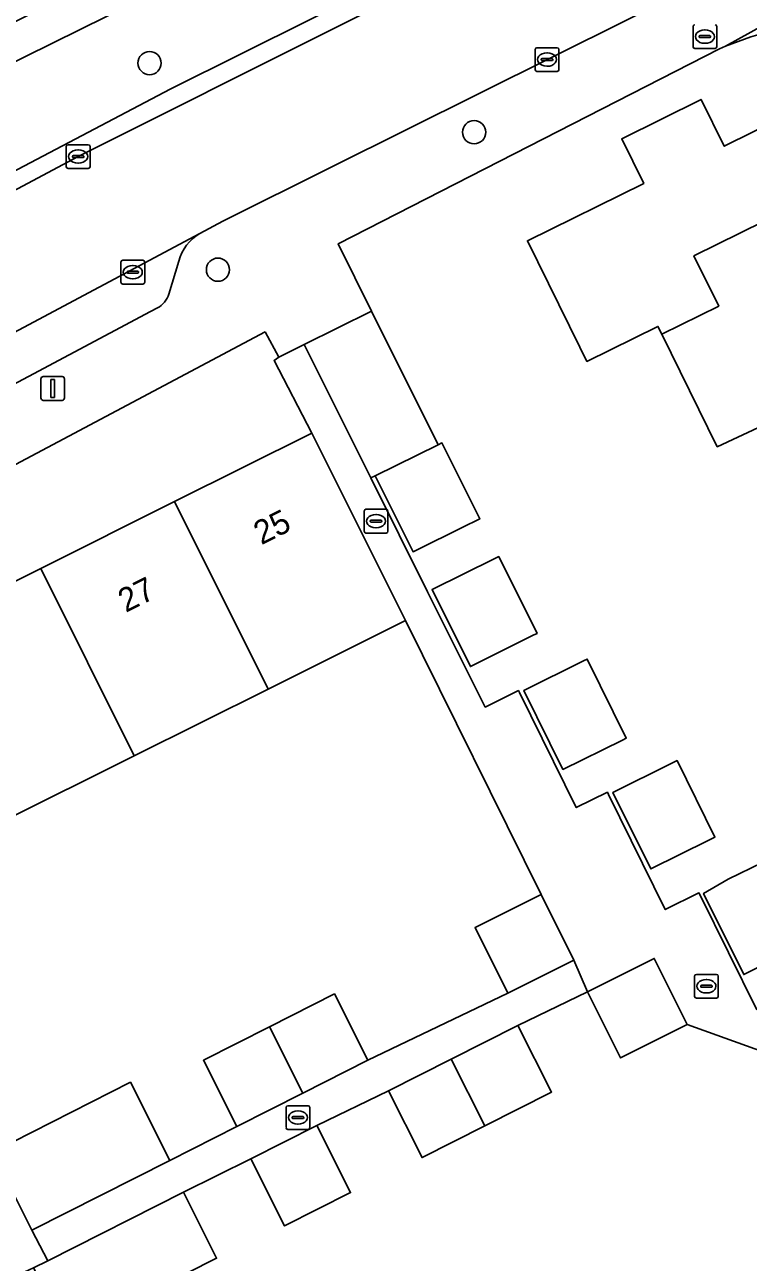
# Model space of a CAD drawing. Extents: x 157793 to 159380, y 380877 to 382313.
# Drawn here: x 158240.9 to 158271.4, y 381573.6 to 381625.7 of the extents above; entities that cross this region are included whole.
import ezdxf

# ---------------------------------------------------------------- set-up
doc = ezdxf.new("R2010")
doc.units = 0
for name, color, linetype in [('IMGEO_Boom', 7, 'Continuous'), ('IMGEO_Brandkraan', 7, 'Continuous'), ('IMGEO_Erf', 7, 'Continuous'), ('IMGEO_Groenvoorziening', 7, 'Continuous'), ('IMGEO_Kolk', 7, 'Continuous'), ('IMGEO_Lichtmast', 7, 'Continuous'), ('IMGEO_Pand', 7, 'Continuous'), ('IMGEO_Pand_nummerreeks', 7, 'Continuous'), ('IMGEO_Parkeervlak_open', 7, 'Continuous'), ('IMGEO_Rijbaan_lokaal_open', 7, 'Continuous'), ('IMGEO_Voetpad_halfverhard', 7, 'Continuous'), ('IMGEO_Voetpad_open', 7, 'Continuous')]:
    doc.layers.add(name, color=color, linetype=linetype)

msp = doc.modelspace()

# ---------------------------------------------------------------- linework, layer by layer
at = {"layer": 'IMGEO_Boom'}
for centre in [(158246.129, 381624.102), (158259.803, 381621.19), (158249.009, 381615.397)]:
    msp.add_circle(centre, 0.489, dxfattribs=at)
at = {"layer": 'IMGEO_Brandkraan'}
for p, q in [((158269.025, 381624.791), (158269.025, 381625.643)), ((158269.513, 381625.497), (158269.538, 381625.497)), ((158270.026, 381625.643), (158270.026, 381624.791)), ((158269.284, 381625.211), (158269.284, 381625.223)), ((158269.722, 381625.174), (158269.324, 381625.174)), ((158269.327, 381625.26), (158269.725, 381625.26)), ((158269.536, 381624.937), (158269.511, 381624.937)), ((158269.768, 381625.223), (158269.768, 381625.211)), ((158269.952, 381624.717), (158269.1, 381624.717))]:
    msp.add_line(p, q, dxfattribs=at)
for points in [[(158269.025, 381624.791), (158269.025, 381625.643)], [(158270.026, 381625.643), (158270.026, 381624.791)], [(158269.952, 381624.717), (158269.1, 381624.717)]]:
    msp.add_lwpolyline(points, dxfattribs=at)
for centre, radius, start, end in [((158269.102, 381625.641), 0.0765, 91.552, 178.448), ((158269.102, 381625.641), 0.0765, 91.552, 178.448), ((158269.95, 381625.641), 0.0765, 1.552, 88.448), ((158269.95, 381625.641), 0.0765, 1.552, 88.448), ((158269.324, 381625.22), 0.0403, 85.8775, 175.7526), ((158269.321, 381625.21), 0.0366, 178.938, 274.7102), ((158269.725, 381625.217), 0.043, 264.8664, 352.4533), ((158269.729, 381625.222), 0.0386, 1.7309, 96.639), ((158269.102, 381624.793), 0.0765, 181.552, 268.448), ((158269.102, 381624.793), 0.0765, 181.552, 268.448), ((158269.95, 381624.793), 0.0765, 271.552, 358.448), ((158269.95, 381624.793), 0.0765, 271.552, 358.448)]:
    msp.add_arc(centre, radius, start, end, dxfattribs=at)
for centre, major_axis, ratio, start_param, end_param in [((158269.512, 381625.217), (-0.387, 0.002), 0.722429, 4.712389, 7.853982), ((158269.537, 381625.217), (-0.39, 0.002), 0.717154, 1.570796, 4.712389)]:
    msp.add_ellipse(centre, major_axis=major_axis, ratio=ratio, start_param=start_param, end_param=end_param, dxfattribs=at)
at = {"layer": 'IMGEO_Erf'}
for points in [[(158271.454, 381625.214), (158270.397, 381624.809), (158270.144, 381624.696), (158254.068, 381616.48), (158255.473, 381613.653), (158258.284, 381608.021), (158258.447, 381608.102), (158260.044, 381604.902), (158259.881, 381604.821), (158259.473, 381604.62), (158257.234, 381603.513), (158255.637, 381606.713), (158255.452, 381606.621), (158257.845, 381601.827), (158260.271, 381596.966), (158261.671, 381597.665), (158261.712, 381597.581), (158264.106, 381592.734), (158265.416, 381593.381), (158265.464, 381593.284), (158267.858, 381588.438), (158269.275, 381589.138), (158269.324, 381589.038), (158271.708, 381584.211)], [(158273.078, 381609.359), (158270.049, 381607.94), (158267.707, 381612.68), (158267.546, 381613.006), (158264.558, 381611.53), (158264.261, 381612.131), (158262.047, 381616.614), (158266.949, 381619.035), (158266.02, 381620.916), (158269.365, 381622.569), (158270.338, 381620.598), (158275.287, 381623.042)], [(158272.878, 381582.118), (158268.783, 381583.589), (158265.976, 381582.187), (158264.582, 381584.978), (158261.649, 381583.558), (158263.069, 381580.749), (158260.254, 381579.326), (158257.611, 381577.99), (158256.191, 381580.799), (158253.173, 381579.335), (158254.598, 381576.517), (158251.816, 381575.111), (158250.391, 381577.929), (158247.551, 381576.528), (158248.955, 381573.75), (158242.644, 381570.559)]]:
    msp.add_lwpolyline(points, dxfattribs=at)
for points in [[(158251.002, 381612.779), (158228.387, 381600.769), (158230.119, 381597.11), (158235.907, 381599.999), (158241.544, 381602.813), (158247.181, 381605.626), (158252.968, 381608.515), (158251.372, 381611.578), (158251.569, 381611.717)], [(158260.677, 381603.227), (158260.84, 381603.308), (158262.454, 381600.075), (158262.291, 381599.994), (158261.93, 381599.813), (158259.649, 381598.675), (158258.03, 381601.918)], [(158239.504, 381578.222), (158245.321, 381581.163), (158246.986, 381577.872), (158249.811, 381579.296), (158248.398, 381582.092), (158251.186, 381583.502), (158253.916, 381584.882), (158255.329, 381582.086), (158261.224, 381584.916), (158259.842, 381587.684), (158262.626, 381589.074), (158256.91, 381600.62), (158251.122, 381597.731), (158245.486, 381594.918), (158239.852, 381592.105), (158234.06, 381589.214)], [(158264.405, 381598.913), (158264.566, 381598.993), (158266.212, 381595.66), (158266.051, 381595.58), (158263.545, 381594.343), (158261.899, 381597.674)], [(158268.106, 381594.59), (158268.356, 381594.713), (158269.948, 381591.49), (158269.698, 381591.367), (158267.243, 381590.154), (158265.651, 381593.376)], [(158271.947, 381590.428), (158272.154, 381590.53), (158273.877, 381587.042), (158273.67, 381586.94), (158271.16, 381585.698), (158269.469, 381589.121), (158270.512, 381589.719)]]:
    msp.add_lwpolyline(points, close=True, dxfattribs=at)
at = {"layer": 'IMGEO_Groenvoorziening'}
for points in [[(158274.259, 381634.674), (158274.211, 381635.262), (158273.634, 381636.615), (158273.46, 381636.828), (158273.2, 381636.691), (158271.78, 381639.651), (158227.145, 381617.595), (158227.622, 381616.703), (158224.921, 381615.32), (158224.432, 381616.254), (158214.514, 381611.353)], [(158247.025, 381623.023), (158264.685, 381631.821), (158269.039, 381633.802)], [(158214.656, 381609.979), (158219.226, 381607.367), (158219.424, 381607.478), (158218.689, 381607.912), (158224.718, 381611.289), (158247.025, 381623.023)]]:
    msp.add_lwpolyline(points, dxfattribs=at)
at = {"layer": 'IMGEO_Kolk'}
for p, q in [((158262.374, 381623.824), (158262.374, 381624.676)), ((158262.449, 381624.75), (158263.301, 381624.75)), ((158262.862, 381624.53), (158262.887, 381624.53)), ((158263.375, 381624.676), (158263.375, 381623.824)), ((158262.633, 381624.244), (158262.633, 381624.256)), ((158263.071, 381624.207), (158262.673, 381624.207)), ((158262.676, 381624.293), (158263.074, 381624.293)), ((158262.885, 381623.97), (158262.86, 381623.97)), ((158263.117, 381624.256), (158263.117, 381624.244)), ((158263.301, 381623.75), (158262.449, 381623.75)), ((158242.619, 381619.738), (158242.619, 381620.59)), ((158242.694, 381620.664), (158243.546, 381620.664)), ((158242.921, 381620.207), (158243.319, 381620.207)), ((158243.107, 381620.444), (158243.132, 381620.444)), ((158243.62, 381620.59), (158243.62, 381619.738)), ((158243.546, 381619.664), (158242.694, 381619.664)), ((158242.878, 381620.158), (158242.878, 381620.17)), ((158243.316, 381620.121), (158242.918, 381620.121)), ((158243.13, 381619.884), (158243.105, 381619.884)), ((158243.362, 381620.17), (158243.362, 381620.158)), ((158244.921, 381614.867), (158244.921, 381615.719)), ((158244.996, 381615.793), (158245.848, 381615.793)), ((158245.409, 381615.573), (158245.434, 381615.573)), ((158245.922, 381615.719), (158245.922, 381614.867)), ((158245.18, 381615.287), (158245.18, 381615.299)), ((158245.618, 381615.25), (158245.22, 381615.25)), ((158245.223, 381615.336), (158245.621, 381615.336)), ((158245.432, 381615.013), (158245.407, 381615.013)), ((158245.664, 381615.299), (158245.664, 381615.287)), ((158245.848, 381614.793), (158244.996, 381614.793)), ((158255.169, 381604.375), (158255.169, 381605.227)), ((158255.244, 381605.301), (158256.096, 381605.301)), ((158255.657, 381605.081), (158255.682, 381605.081)), ((158256.17, 381605.227), (158256.17, 381604.375)), ((158255.428, 381604.795), (158255.428, 381604.807)), ((158255.866, 381604.758), (158255.468, 381604.758)), ((158255.471, 381604.844), (158255.869, 381604.844)), ((158255.912, 381604.807), (158255.912, 381604.795)), ((158256.096, 381604.301), (158255.244, 381604.301)), ((158255.68, 381604.521), (158255.655, 381604.521)), ((158269.09, 381584.78), (158269.09, 381585.632)), ((158269.165, 381585.706), (158270.017, 381585.706)), ((158269.578, 381585.486), (158269.603, 381585.486)), ((158270.091, 381585.632), (158270.091, 381584.78)), ((158269.349, 381585.2), (158269.349, 381585.212)), ((158269.787, 381585.163), (158269.389, 381585.163)), ((158269.392, 381585.249), (158269.79, 381585.249)), ((158269.601, 381584.926), (158269.576, 381584.926)), ((158269.833, 381585.212), (158269.833, 381585.2)), ((158270.017, 381584.706), (158269.165, 381584.706)), ((158251.88, 381579.249), (158251.88, 381580.101)), ((158251.955, 381580.175), (158252.807, 381580.175)), ((158252.881, 381580.101), (158252.881, 381579.249)), ((158252.139, 381579.669), (158252.139, 381579.681)), ((158252.577, 381579.632), (158252.179, 381579.632)), ((158252.182, 381579.718), (158252.58, 381579.718)), ((158252.368, 381579.955), (158252.393, 381579.955)), ((158252.623, 381579.681), (158252.623, 381579.669)), ((158252.807, 381579.175), (158251.955, 381579.175)), ((158252.391, 381579.395), (158252.366, 381579.395))]:
    msp.add_line(p, q, dxfattribs=at)
for points in [[(158262.374, 381623.824), (158262.374, 381624.676)], [(158262.449, 381624.75), (158263.301, 381624.75)], [(158263.375, 381624.676), (158263.375, 381623.824)], [(158263.301, 381623.75), (158262.449, 381623.75)], [(158242.619, 381619.738), (158242.619, 381620.59)], [(158242.694, 381620.664), (158243.546, 381620.664)], [(158243.62, 381620.59), (158243.62, 381619.738)], [(158243.546, 381619.664), (158242.694, 381619.664)], [(158244.921, 381614.867), (158244.921, 381615.719)], [(158244.996, 381615.793), (158245.848, 381615.793)], [(158245.922, 381615.719), (158245.922, 381614.867)], [(158245.848, 381614.793), (158244.996, 381614.793)], [(158255.169, 381604.375), (158255.169, 381605.227)], [(158255.244, 381605.301), (158256.096, 381605.301)], [(158256.17, 381605.227), (158256.17, 381604.375)], [(158256.096, 381604.301), (158255.244, 381604.301)], [(158269.09, 381584.78), (158269.09, 381585.632)], [(158269.165, 381585.706), (158270.017, 381585.706)], [(158270.091, 381585.632), (158270.091, 381584.78)], [(158270.017, 381584.706), (158269.165, 381584.706)], [(158251.88, 381579.249), (158251.88, 381580.101)], [(158251.955, 381580.175), (158252.807, 381580.175)], [(158252.881, 381580.101), (158252.881, 381579.249)], [(158252.807, 381579.175), (158251.955, 381579.175)]]:
    msp.add_lwpolyline(points, dxfattribs=at)
for centre, radius, start, end in [((158262.451, 381624.674), 0.0765, 91.552, 178.448), ((158262.451, 381624.674), 0.0765, 91.552, 178.448), ((158263.299, 381624.674), 0.0765, 1.552, 88.448), ((158263.299, 381624.674), 0.0765, 1.552, 88.448), ((158262.673, 381624.253), 0.0403, 85.8775, 175.7526), ((158262.67, 381624.243), 0.0366, 178.938, 274.7102), ((158263.074, 381624.25), 0.043, 264.8664, 352.4533), ((158263.078, 381624.255), 0.0386, 1.7309, 96.639), ((158262.451, 381623.826), 0.0765, 181.552, 268.448), ((158262.451, 381623.826), 0.0765, 181.552, 268.448), ((158263.299, 381623.826), 0.0765, 271.552, 358.448), ((158263.299, 381623.826), 0.0765, 271.552, 358.448), ((158242.696, 381620.588), 0.0765, 91.552, 178.448), ((158242.696, 381620.588), 0.0765, 91.552, 178.448), ((158242.918, 381620.167), 0.0403, 85.8775, 175.7526), ((158243.323, 381620.169), 0.0386, 1.7309, 96.639), ((158243.544, 381620.588), 0.0765, 1.552, 88.448), ((158243.544, 381620.588), 0.0765, 1.552, 88.448), ((158242.696, 381619.74), 0.0765, 181.552, 268.448), ((158242.696, 381619.74), 0.0765, 181.552, 268.448), ((158242.915, 381620.157), 0.0366, 178.938, 274.7102), ((158243.319, 381620.164), 0.043, 264.8664, 352.4533), ((158243.544, 381619.74), 0.0765, 271.552, 358.448), ((158243.544, 381619.74), 0.0765, 271.552, 358.448), ((158244.998, 381615.717), 0.0765, 91.552, 178.448), ((158244.998, 381615.717), 0.0765, 91.552, 178.448), ((158245.846, 381615.717), 0.0765, 1.552, 88.448), ((158245.846, 381615.717), 0.0765, 1.552, 88.448), ((158245.22, 381615.296), 0.0403, 85.8775, 175.7526), ((158245.217, 381615.286), 0.0366, 178.938, 274.7102), ((158245.621, 381615.293), 0.043, 264.8664, 352.4533), ((158245.625, 381615.298), 0.0386, 1.7309, 96.639), ((158244.998, 381614.869), 0.0765, 181.552, 268.448), ((158244.998, 381614.869), 0.0765, 181.552, 268.448), ((158245.846, 381614.869), 0.0765, 271.552, 358.448), ((158245.846, 381614.869), 0.0765, 271.552, 358.448), ((158255.246, 381605.225), 0.0765, 91.552, 178.448), ((158255.246, 381605.225), 0.0765, 91.552, 178.448), ((158256.094, 381605.225), 0.0765, 1.552, 88.448), ((158256.094, 381605.225), 0.0765, 1.552, 88.448), ((158255.468, 381604.804), 0.0403, 85.8775, 175.7526), ((158255.465, 381604.794), 0.0366, 178.938, 274.7102), ((158255.869, 381604.801), 0.043, 264.8664, 352.4533), ((158255.873, 381604.806), 0.0386, 1.7309, 96.639), ((158255.246, 381604.377), 0.0765, 181.552, 268.448), ((158255.246, 381604.377), 0.0765, 181.552, 268.448), ((158256.094, 381604.377), 0.0765, 271.552, 358.448), ((158256.094, 381604.377), 0.0765, 271.552, 358.448), ((158269.167, 381585.63), 0.0765, 91.552, 178.448), ((158269.167, 381585.63), 0.0765, 91.552, 178.448), ((158270.015, 381585.63), 0.0765, 1.552, 88.448), ((158270.015, 381585.63), 0.0765, 1.552, 88.448), ((158269.167, 381584.782), 0.0765, 181.552, 268.448), ((158269.167, 381584.782), 0.0765, 181.552, 268.448), ((158269.389, 381585.209), 0.0403, 85.8775, 175.7526), ((158269.386, 381585.199), 0.0366, 178.938, 274.7102), ((158269.79, 381585.206), 0.043, 264.8664, 352.4533), ((158269.794, 381585.211), 0.0386, 1.7309, 96.639), ((158270.015, 381584.782), 0.0765, 271.552, 358.448), ((158270.015, 381584.782), 0.0765, 271.552, 358.448), ((158251.957, 381580.099), 0.0765, 91.552, 178.448), ((158251.957, 381580.099), 0.0765, 91.552, 178.448), ((158252.805, 381580.099), 0.0765, 1.552, 88.448), ((158252.805, 381580.099), 0.0765, 1.552, 88.448), ((158252.179, 381579.678), 0.0403, 85.8775, 175.7526), ((158252.176, 381579.668), 0.0366, 178.938, 274.7102), ((158252.58, 381579.675), 0.043, 264.8664, 352.4533), ((158252.584, 381579.68), 0.0386, 1.7309, 96.639), ((158251.957, 381579.251), 0.0765, 181.552, 268.448), ((158251.957, 381579.251), 0.0765, 181.552, 268.448), ((158252.805, 381579.251), 0.0765, 271.552, 358.448), ((158252.805, 381579.251), 0.0765, 271.552, 358.448)]:
    msp.add_arc(centre, radius, start, end, dxfattribs=at)
for centre, major_axis, ratio, start_param, end_param in [((158262.861, 381624.25), (-0.387, 0.002), 0.722429, 4.712389, 7.853982), ((158262.886, 381624.25), (-0.39, 0.002), 0.717154, 1.570796, 4.712389), ((158243.106, 381620.164), (-0.387, 0.002), 0.722429, 4.712389, 7.853982), ((158243.131, 381620.164), (-0.39, 0.002), 0.717154, 1.570796, 4.712389), ((158245.408, 381615.293), (-0.387, 0.002), 0.722429, 4.712389, 7.853982), ((158245.433, 381615.293), (-0.39, 0.002), 0.717154, 1.570796, 4.712389), ((158255.656, 381604.801), (-0.387, 0.002), 0.722429, 4.712389, 7.853982), ((158255.681, 381604.801), (-0.39, 0.002), 0.717154, 1.570796, 4.712389), ((158269.577, 381585.206), (-0.387, 0.002), 0.722429, 4.712389, 7.853982), ((158269.602, 381585.206), (-0.39, 0.002), 0.717154, 1.570796, 4.712389), ((158252.367, 381579.675), (-0.387, 0.002), 0.722429, 4.712389, 7.853982), ((158252.392, 381579.675), (-0.39, 0.002), 0.717154, 1.570796, 4.712389)]:
    msp.add_ellipse(centre, major_axis=major_axis, ratio=ratio, start_param=start_param, end_param=end_param, dxfattribs=at)
at = {"layer": 'IMGEO_Lichtmast'}
for p, q in [((158241.652, 381610.893), (158242.442, 381610.893)), ((158242.442, 381610.893), (158241.652, 381610.893)), ((158241.552, 381609.993), (158241.552, 381610.793)), ((158241.552, 381610.793), (158241.552, 381609.993)), ((158242.542, 381610.793), (158242.542, 381609.993)), ((158242.542, 381609.993), (158242.542, 381610.793)), ((158242.442, 381609.893), (158241.652, 381609.893)), ((158241.652, 381609.893), (158242.442, 381609.893))]:
    msp.add_line(p, q, dxfattribs=at)
msp.add_lwpolyline([(158241.972, 381610.768), (158242.122, 381610.768), (158242.122, 381610.018), (158241.972, 381610.018), (158241.972, 381610.768)], dxfattribs=at)
for centre, start, end in [((158241.652, 381610.793), 90, 180), ((158241.652, 381610.793), 90, 180), ((158242.442, 381610.793), 0, 90), ((158242.442, 381610.793), 360, 90), ((158241.652, 381609.993), 180, 270), ((158241.652, 381609.993), 180, 270), ((158242.442, 381609.993), 270, 0), ((158242.442, 381609.993), 270, 0)]:
    msp.add_arc(centre, 0.1, start, end, dxfattribs=at)
at = {"layer": 'IMGEO_Pand'}
for points in [[(158267.707, 381612.68), (158270.106, 381613.866), (158269.062, 381615.977), (158274.952, 381618.89), (158276.87, 381619.837), (158275.287, 381623.042), (158270.338, 381620.598), (158269.365, 381622.569), (158266.02, 381620.916), (158266.949, 381619.035), (158262.047, 381616.614), (158264.261, 381612.131), (158264.558, 381611.53), (158267.546, 381613.006)], [(158267.707, 381612.68), (158270.049, 381607.94), (158273.078, 381609.359), (158275.248, 381610.432), (158274.153, 381612.645), (158279.146, 381615.116), (158277.561, 381618.323), (158275.689, 381617.398), (158274.952, 381618.89), (158269.062, 381615.977), (158270.106, 381613.866)], [(158255.473, 381613.653), (158252.646, 381612.242), (158255.452, 381606.621), (158255.637, 381606.713), (158258.284, 381608.021)], [(158247.181, 381605.626), (158251.122, 381597.731), (158256.91, 381600.62), (158252.968, 381608.515)], [(158258.447, 381608.102), (158258.284, 381608.021), (158255.637, 381606.713), (158257.234, 381603.513), (158259.473, 381604.62), (158259.881, 381604.821), (158260.044, 381604.902)], [(158245.486, 381594.918), (158251.122, 381597.731), (158247.181, 381605.626), (158241.544, 381602.813)], [(158260.677, 381603.227), (158258.03, 381601.918), (158259.649, 381598.675), (158261.93, 381599.813), (158262.291, 381599.994), (158262.454, 381600.075), (158260.84, 381603.308)], [(158239.852, 381592.105), (158245.486, 381594.918), (158241.544, 381602.813), (158235.907, 381599.999)], [(158264.405, 381598.913), (158261.899, 381597.674), (158263.545, 381594.343), (158266.051, 381595.58), (158266.212, 381595.66), (158264.566, 381598.993)], [(158268.106, 381594.59), (158265.651, 381593.376), (158267.243, 381590.154), (158269.698, 381591.367), (158269.948, 381591.49), (158268.356, 381594.713)], [(158271.947, 381590.428), (158270.512, 381589.719), (158269.469, 381589.121), (158271.16, 381585.698), (158273.67, 381586.94), (158273.877, 381587.042), (158272.154, 381590.53)], [(158261.224, 381584.916), (158264.008, 381586.306), (158262.626, 381589.074), (158259.842, 381587.684)], [(158268.783, 381583.589), (158267.389, 381586.38), (158264.582, 381584.978), (158265.976, 381582.187)], [(158252.586, 381580.699), (158255.329, 381582.086), (158253.916, 381584.882), (158251.186, 381583.502)], [(158252.586, 381580.699), (158251.186, 381583.502), (158248.398, 381582.092), (158249.811, 381579.296)], [(158258.834, 381582.135), (158260.254, 381579.326), (158263.069, 381580.749), (158261.649, 381583.558)], [(158258.834, 381582.135), (158256.191, 381580.799), (158257.611, 381577.99), (158260.254, 381579.326)], [(158241.168, 381574.93), (158246.986, 381577.872), (158245.321, 381581.163), (158239.504, 381578.222)], [(158250.391, 381577.929), (158251.816, 381575.111), (158254.598, 381576.517), (158253.173, 381579.335)], [(158241.24, 381573.337), (158242.644, 381570.559), (158248.955, 381573.75), (158247.551, 381576.528), (158241.845, 381573.643)]]:
    msp.add_lwpolyline(points, close=True, dxfattribs=at)
at = {"layer": 'IMGEO_Parkeervlak_open'}
for points in [[(158248.241, 381616.921), (158227.022, 381605.619)], [(158246.945, 381614.369), (158247.356, 381615.76)], [(158230.525, 381605.311), (158246.171, 381613.631), (158246.46, 381613.785)]]:
    msp.add_lwpolyline(points, dxfattribs=at)
for centre, radius, start, end in [((158249.25, 381615.234), 1.966, 120.8908, 164.4746), ((158245.929, 381614.719), 1.075, 299.6064, 340.9758)]:
    msp.add_arc(centre, radius, start, end, dxfattribs=at)
at = {"layer": 'IMGEO_Rijbaan_lokaal_open'}
msp.add_lwpolyline([(158273.591, 381633.934), (158271.644, 381633.72), (158270.035, 381633.294), (158264.837, 381631.057), (158243.12, 381620.164), (158224.426, 381610.205), (158227.022, 381605.619), (158248.241, 381616.921), (158249.211, 381617.443), (158253.814, 381619.732), (158269.354, 381627.481)], dxfattribs=at)
at = {"layer": 'IMGEO_Voetpad_halfverhard'}
msp.add_lwpolyline([(158224.432, 381616.254), (158227.145, 381617.595), (158271.78, 381639.651), (158271.114, 381641.038), (158216.977, 381614.225), (158213.045, 381612.278)], dxfattribs=at)
at = {"layer": 'IMGEO_Voetpad_open'}
for points in [[(158269.039, 381633.802), (158264.685, 381631.821), (158247.025, 381623.023), (158224.718, 381611.289), (158218.689, 381607.912), (158219.424, 381607.478), (158224.426, 381610.205), (158243.12, 381620.164), (158264.837, 381631.057), (158270.035, 381633.294), (158271.644, 381633.72), (158273.591, 381633.934)], [(158251.002, 381612.779), (158251.569, 381611.717), (158252.646, 381612.242), (158255.473, 381613.653), (158254.068, 381616.48), (158270.144, 381624.696), (158270.397, 381624.809), (158277.463, 381628.739), (158275.469, 381628.798)], [(158277.463, 381628.739), (158270.397, 381624.809), (158271.454, 381625.214), (158272.542, 381625.522), (158273.654, 381625.731)], [(158269.354, 381627.481), (158253.814, 381619.732), (158249.211, 381617.443), (158248.241, 381616.921)], [(158247.356, 381615.76), (158246.945, 381614.369)], [(158246.46, 381613.785), (158246.171, 381613.631), (158230.525, 381605.311)], [(158224.274, 381601), (158225.527, 381598.112), (158225.89, 381597.35), (158225.982, 381597.392), (158227.677, 381598.247), (158227.95, 381598.381), (158227.103, 381600.073), (158228.387, 381600.769), (158251.002, 381612.779)], [(158271.708, 381584.211), (158269.324, 381589.038), (158269.275, 381589.138), (158267.858, 381588.438), (158265.464, 381593.284), (158265.416, 381593.381), (158264.106, 381592.734), (158261.712, 381597.581), (158261.671, 381597.665), (158260.271, 381596.966), (158257.845, 381601.827), (158255.452, 381606.621), (158252.646, 381612.242), (158251.569, 381611.717), (158251.372, 381611.578), (158252.968, 381608.515), (158256.91, 381600.62), (158262.626, 381589.074), (158264.008, 381586.306), (158264.582, 381584.978), (158267.389, 381586.38), (158268.783, 381583.589), (158272.878, 381582.118)]]:
    msp.add_lwpolyline(points, dxfattribs=at)
for points in [[(158239.504, 381578.222), (158234.06, 381589.214), (158230.119, 381597.11), (158228.387, 381600.769), (158227.103, 381600.073), (158227.95, 381598.381), (158227.677, 381598.247), (158237.83, 381577.762), (158235.941, 381576.836), (158245.054, 381558.421), (158249.583, 381549.497), (158252.887, 381542.755), (158254.456, 381543.47), (158253.32, 381545.944), (158248.865, 381555.221), (158247.175, 381558.564), (158241.542, 381570.002), (158240.144, 381572.842), (158241.24, 381573.337), (158241.845, 381573.643), (158241.168, 381574.93)], [(158261.649, 381583.558), (158264.582, 381584.978), (158264.008, 381586.306), (158261.224, 381584.916), (158255.329, 381582.086), (158252.586, 381580.699), (158249.811, 381579.296), (158246.986, 381577.872), (158241.168, 381574.93), (158241.845, 381573.643), (158247.551, 381576.528), (158250.391, 381577.929), (158253.173, 381579.335), (158256.191, 381580.799), (158258.834, 381582.135)]]:
    msp.add_lwpolyline(points, close=True, dxfattribs=at)
for centre, radius, start, end in [((158249.25, 381615.234), 1.966, 120.8908, 164.4746), ((158245.929, 381614.719), 1.075, 299.6064, 340.9758)]:
    msp.add_arc(centre, radius, start, end, dxfattribs=at)

# ---------------------------------------------------------------- texts
at = {"layer": 'IMGEO_Pand_nummerreeks'}
for s, p in [('25', (158250.838, 381603.786)), ('27', (158245.126, 381600.934))]:
    msp.add_text(s, height=1, rotation=26.5259, dxfattribs=at).set_placement(p)

doc.saveas('drawing.dxf')
